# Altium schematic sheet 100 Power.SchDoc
size Letter; Organization: Toradex Solutions Inc.; Address1: 6415 Northwest Drive; Address2: Mississauga, ON, L4V 1X1; Address3: Canada
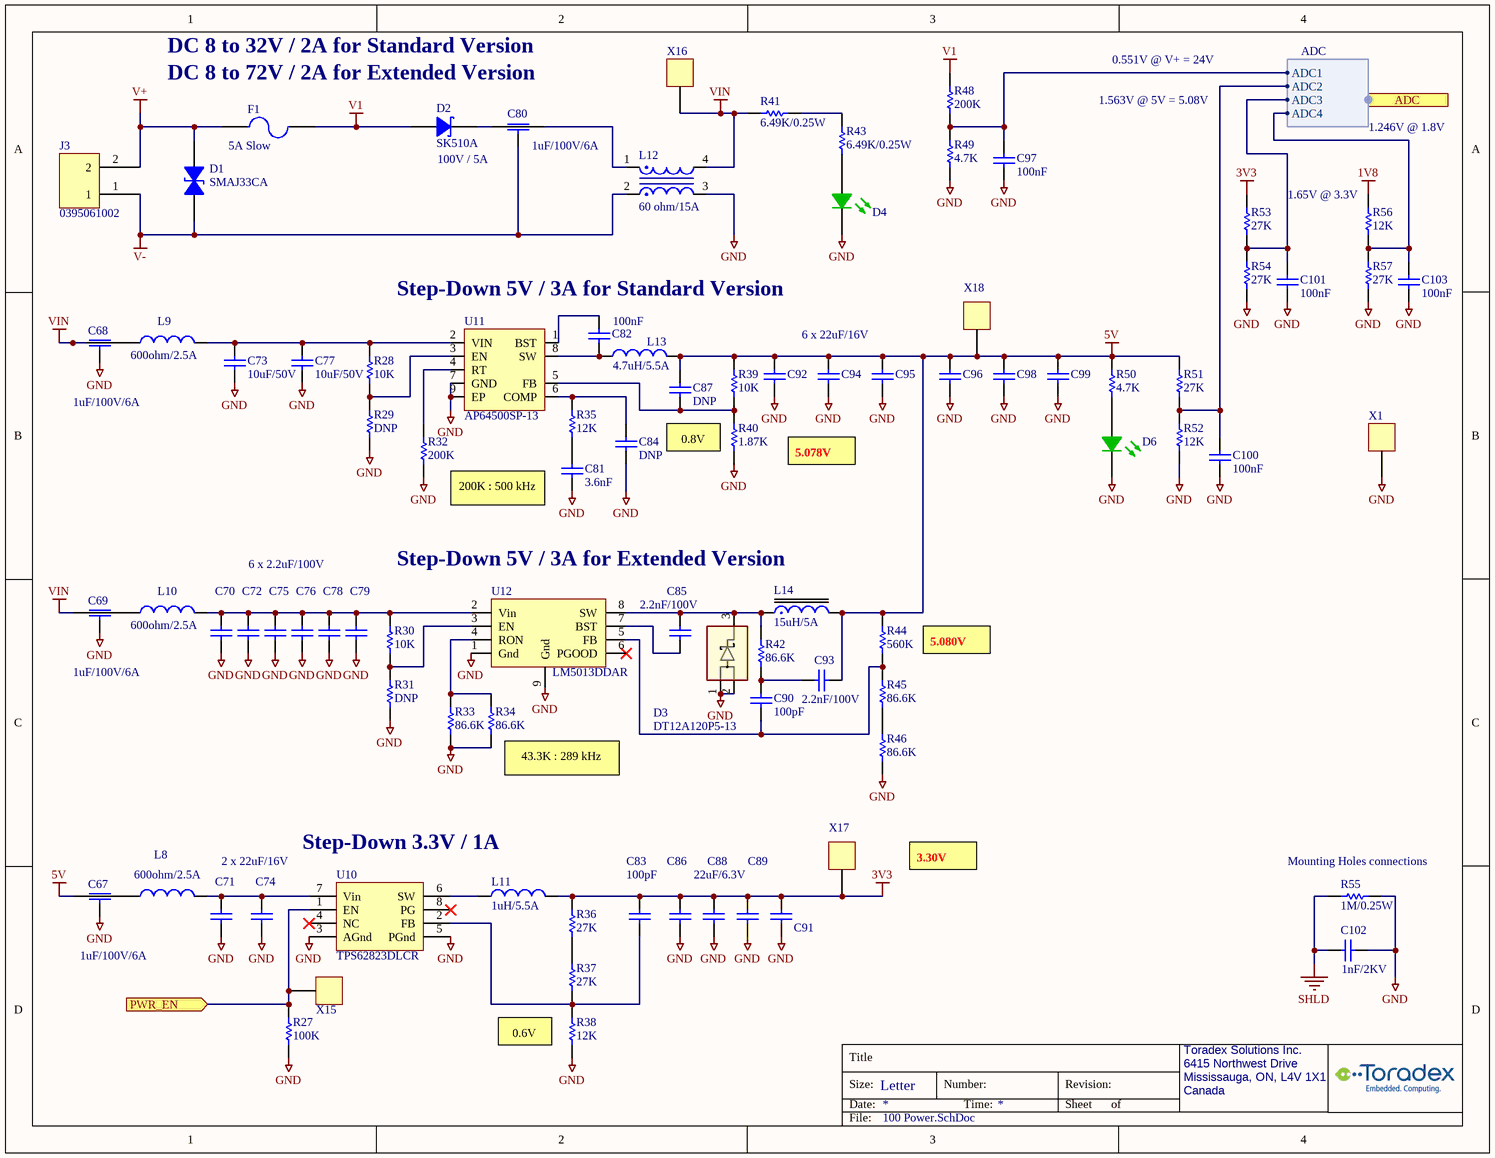
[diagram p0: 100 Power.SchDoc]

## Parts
C67  value 1uF/100V/6A  [C/1206_3P]  (hidden comment: 0753-Cap 3P-1206-1uF/100V/6A)
C68  value 1uF/100V/6A  [C/1206_3P]  (hidden comment: 0753-Cap 3P-1206-1uF/100V/6A)
C69  value 1uF/100V/6A  [C/1206_3P]  (hidden comment: 0753-Cap 3P-1206-1uF/100V/6A)
C70  CC1206KKX7R0BB225  [C/1206]  (value not drawn)
C71  1314-Cap-0805-22uF/16V  [C/0805]  (value not drawn)
C72  CC1206KKX7R0BB225  [C/1206]  (value not drawn)
C73  10uF/50V  [CAPC3225N]
C74  1314-Cap-0805-22uF/16V  [C/0805]  (value not drawn)
C75  CC1206KKX7R0BB225  [C/1206]  (value not drawn)
C76  CC1206KKX7R0BB225  [C/1206]  (value not drawn)
C77  10uF/50V  [CAPC3225N]
C78  CC1206KKX7R0BB225  [C/1206]  (value not drawn)
C79  CC1206KKX7R0BB225  [C/1206]  (value not drawn)
C80  value 1uF/100V/6A  [C/1206_3P]  (hidden comment: 0753-Cap 3P-1206-1uF/100V/6A)
C81  value 3.6nF  [C/0603]  (hidden comment: 1470-Cap-0603-3.6nF)
C82  100nF  [C0402_CAPC1005L]
C83  value 100pF  [C0402_CAPC1005L]  (hidden comment: 1602-Cap-0402-100pF)
C84  value DNP  [C/0603]  (hidden comment: 0000-Cap-0603-DNP)
C85  value 2.2nF/100V  [C/0603]  (hidden comment: 1875-Cap-0603-2.2nF/100V)
C86  22uF/6.3V  [C0402_CAPC1005L]
C87  value DNP  [C/0603]  (hidden comment: 0000-Cap-0603-DNP)
C88  22uF/6.3V  [C0402_CAPC1005L]  (value not drawn)
C89  22uF/6.3V  [C0402_CAPC1005L]  (value not drawn)
C90  value 100pF  [C0402_CAPC1005L]  (hidden comment: 1602-Cap-0402-100pF)
C91  22uF/6.3V  [C0402_CAPC1005L]  (value not drawn)
C92  1314-Cap-0805-22uF/16V  [C/0805]  (value not drawn)
C93  value 2.2nF/100V  [C/0603]  (hidden comment: 1875-Cap-0603-2.2nF/100V)
C94  1314-Cap-0805-22uF/16V  [C/0805]  (value not drawn)
C95  1314-Cap-0805-22uF/16V  [C/0805]  (value not drawn)
C96  1314-Cap-0805-22uF/16V  [C/0805]  (value not drawn)
C97  100nF  [C0402_CAPC1005L]
C98  1314-Cap-0805-22uF/16V  [C/0805]  (value not drawn)
C99  1314-Cap-0805-22uF/16V  [C/0805]  (value not drawn)
C100  100nF  [C0402_CAPC1005L]
C101  100nF  [C0402_CAPC1005L]
C102  value 1nF/2KV  [C/1206]  (hidden comment: 0567-Cap-1206-1nF/2KV)
C103  100nF  [C0402_CAPC1005L]
D1  SMAJ33CA  [SMAJ_TRANSIL]
D2  SK510A  [SMAJ]
D3  DT12A120P5-13  [POWERDI-5_DIO]
D4  Status  [LED-SMT-0603_APT1608CGCK]  (value not drawn)
D6  Status  [LED-SMT-0603_APT1608CGCK]  (value not drawn)
F1  5A Slow  [FUSC6125X279N]
J3  0395061002  [Phoenix_1727566]
L8  value 600ohm/2.5A  [INDP1206]  (hidden comment: 1641-Fer-1206-600ohm/2.5A)
L9  value 600ohm/2.5A  [INDP1206]  (hidden comment: 1641-Fer-1206-600ohm/2.5A)
L10  value 600ohm/2.5A  [INDP1206]  (hidden comment: 1641-Fer-1206-600ohm/2.5A)
L11  value 1uH/5.5A  [INDC3225N]  (hidden comment: NS10165T4R7NNA)
L12  60 ohm/15A  [COMMON_CHOKE_Laird_CM3421Y600R-10]
L13  value 4.7uH/5.5A  [INDP_7.3X6.6N]  (hidden comment: BMRA000606304R7MA1)
L14  value 15uH/5A  [EATON_DR127]  (hidden comment: DR127-150-R)
R27  value 100K  [R0402_RESC1005L]  (hidden comment: 1977-Res-0402-100K)
R28  value 10K  [R0402_RESC1005L]  (hidden comment: 1572-Res-0402-10K)
R29  value DNP  [R/0603]  (hidden comment: 0000-Res-0603-DNP)
R30  value 10K  [R0402_RESC1005L]  (hidden comment: 1572-Res-0402-10K)
R31  value DNP  [R/0603]  (hidden comment: 0000-Res-0603-DNP)
R32  value 200K  [R/0603]  (hidden comment: 1367-Res-0603-200K)
R33  value 86.6K  [R0402_RESC1005L]  (hidden comment: 1539-Res-0402-86.6k)
R34  value 86.6K  [R0402_RESC1005L]  (hidden comment: 1539-Res-0402-86.6k)
R35  value 12K  [R0402_RESC1005L]  (hidden comment: 1537-Res-0402-12K)
R36  value 27K  [R0402_RESC1005L]  (hidden comment: 1538-Res-0402-27k)
R37  value 27K  [R0402_RESC1005L]  (hidden comment: 1538-Res-0402-27k)
R38  value 12K  [R0402_RESC1005L]  (hidden comment: 1537-Res-0402-12K)
R39  value 10K  [R0402_RESC1005L]  (hidden comment: 1572-Res-0402-10K)
R40  value 1.87K  [R0402_RESC1005L]  (hidden comment: 1536-Res-0402-1.87K)
R41  value 6.49K/0.25W  [R/0805]  (hidden comment: 1603-Res-0805-6.49K/0.25W)
R42  value 86.6K  [R0402_RESC1005L]  (hidden comment: 1539-Res-0402-86.6k)
R43  value 6.49K/0.25W  [R/0805]  (hidden comment: 1603-Res-0805-6.49K/0.25W)
R44  value 560K  [R/0603]  (hidden comment: 1876-Res-0603-560K)
R45  value 86.6K  [R0402_RESC1005L]  (hidden comment: 1539-Res-0402-86.6k)
R46  value 86.6K  [R0402_RESC1005L]  (hidden comment: 1539-Res-0402-86.6k)
R48  value 200K  [R/0603]  (hidden comment: 1367-Res-0603-200K)
R49  value 4.7K  [R0402_RESC1005L]  (hidden comment: 2233-Res-0402-4.7K)
R50  value 4.7K  [R0402_RESC1005L]  (hidden comment: 2233-Res-0402-4.7K)
R51  value 27K  [R0402_RESC1005L]  (hidden comment: 1538-Res-0402-27k)
R52  value 12K  [R0402_RESC1005L]  (hidden comment: 1537-Res-0402-12K)
R53  value 27K  [R0402_RESC1005L]  (hidden comment: 1538-Res-0402-27k)
R54  value 27K  [R0402_RESC1005L]  (hidden comment: 1538-Res-0402-27k)
R55  value 1M/0.25W  [R/1206]  (hidden comment: 1860-Res-1206-1M-5%-0.25W)
R56  value 12K  [R0402_RESC1005L]  (hidden comment: 1537-Res-0402-12K)
R57  value 27K  [R0402_RESC1005L]  (hidden comment: 1538-Res-0402-27k)
U10  TPS62823DLCR  [DLC0008A]
U11  AP64500SP-13  [SOP-9 TP_ALT]
U12  LM5013DDAR  [SOP-9 TP]
X1  000-TestPoint  [TestPoint_1]  (value not drawn)
X15  000-TestPoint  [TestPoint_1]  (value not drawn)
X16  000-TestPoint  [TestPoint_1]  (value not drawn)
X17  000-TestPoint  [TestPoint_1]  (value not drawn)
X18  000-TestPoint  [TestPoint_1]  (value not drawn)

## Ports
ADC (harness ADC), PWR_EN (in)

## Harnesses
ADC: ADC1, ADC2, ADC3, ADC4

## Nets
1V8: R56.2
3V3: C83.2 C86.2 C88.2 C89.2 C91.2 L11.2 R36.2 R53.2 X17.1
5V: C67.1(In/Out) C87.1 C92.2 C93.2 C94.2 C95.2 C96.2 C98.2 C99.2 L13.2 L14.2 R39.2 R44.2 R50.2 R51.2 X18.1
GND: C67.2(Gnd) C68.2(Gnd) C69.2(Gnd) C70.1 C71.1 C72.1 C73.1 C74.1 C75.1 C76.1 C77.1 C78.1 C79.1 C81.2 C84.2 C86.1 C88.1 C89.1 C91.1 C92.1 C94.1 C95.1 C96.1 C97.2 C98.1 C99.1 C100.2 C101.2 C102.1 C103.2 D3.1 D3.2 D4.2(K) D6.2(K) L12.3 R27.1 R29.2 R31.2 R32.1 R33.1 R34.1 R38.1 R40.1 R46.1 R49.1 R52.1 R54.1 R55.2 R57.1 U10.3(AGnd) U10.5(PGnd) U11.7(GND) U11.9(EP) U12.1(Gnd) U12.9(Gnd) X1.1
SHLD: C102.2 R55.1
V1: D2.1(A) F1.2 R48.2
V+: D1.2 F1.1 J3.2
V-: C80.2(Gnd) D1.1 J3.1 L12.2
VIN: C68.1(In/Out) C69.1(In/Out) L12.4 R41.1 X16.1
PWR_EN: R27.2 U10.1(EN) X15.1 ; port PWR_EN
NetC67_3: C67.3(In/Out) L8.1
NetC68_3: C68.3(In/Out) L9.1
NetC69_3: C69.3(In/Out) L10.1
NetC70_2: C70.2 C72.2 C75.2 C76.2 C78.2 C79.2 L10.2 R30.2 U12.2(Vin)
NetC71_2: C71.2 C74.2 L8.2 U10.7(Vin)
NetC73_2: C73.2 C77.2 L9.2 R28.2 U11.2(VIN)
NetC80_1: C80.1(In/Out) D2.2(K)
NetC80_3: C80.3(In/Out) L12.1
NetC81_1: C81.1 R35.1
NetC82_1: C82.1 U11.1(BST)
NetC82_2: C82.2 L13.1 U11.8(SW)
NetC83_1: C83.1 R37.1 R38.2 U10.2(FB)
NetC84_1: C84.1 R35.2 U11.6(COMP)
NetC85_1: C85.1 D3.3 L14.1 R42.2 U12.8(SW)
NetC85_2: C85.2 U12.7(BST)
NetC87_2: C87.2 R39.1 R40.2 U11.5(FB)
NetC90_1: C90.1 R44.1 R45.2 U12.5(FB)
NetC90_2: C90.2 C93.1 R42.1
NetC97_1: C97.1 R48.1 R49.2 ; port ADC.ADC1
NetC100_1: C100.1 R51.1 R52.2 ; port ADC.ADC2
NetC101_1: C101.1 R53.1 R54.2 ; port ADC.ADC3
NetC103_1: C103.1 R56.1 R57.2 ; port ADC.ADC4
NetD4_1: D4.1(A) R43.2
NetD6_1: D6.1(A) R50.1
NetL11_1: L11.1 U10.6(SW)
NetR28_1: R28.1 R29.1 U11.3(EN)
NetR30_1: R30.1 R31.1 U12.3(EN)
NetR32_2: R32.2 U11.4(RT)
NetR33_2: R33.2 R34.2 U12.4(RON)
NetR36_1: R36.1 R37.2
NetR41_2: R41.2 R43.1
NetR45_1: R45.1 R46.2

Not connected (* = marked no-connect by the designer): U10 4(NC)* 8(PG)*; U12 6(PGOOD)*

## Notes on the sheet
- DC 8 to 32V / 2A for Standard Version
- DC 8 to 72V / 2A for Extended Version
- 1.563V @ 5V = 5.08V
- 0.551V @ V+ = 24V
- 100V / 5A
- 1.246V @ 1.8V
- (near R56) 1.65V @ 3.3V
- Step-Down 5V / 3A for Standard Version
- 6 x 22uF/16V
- 200K : 500 kHz
- (near R40) 0.8V
- 5.078V
- 6 x 2.2uF/100V
- Step-Down 5V / 3A for Extended Version
- 5.080V
- (near R34) 43.3K : 289 kHz
- 2 x 22uF/16V
- Step-Down 3.3V / 1A
- 3.30V
- (near R55) Mounting Holes connections
- 0.6V

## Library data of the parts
C67-C69 C80 = 0753-Cap 3P-1206-1uF/100V/6A: (-55 to 125 DegC) CAP FEEDTHRU 1UF 20% 100V 1206 6A; Mfr: TDK Corporation; MfrNo: YFF31HC2A105MT000N; PN: 753; Alt: YFF31AH2A105MT0Y0N
C70 C72 C75 C76 C78 C79 = 1873-Cap-1206-2.2uF/100V: (-55 to 125 DegC) CAP CER 2.2UF 100V 10% X7R 1206; Mfr: Yageo; PN: 1873
C71 C74 C92 C94-C96 C98 C99 = 1314-Cap-0805-22uF/16V: (-55 to 85 DegC) CAP CER 22uF 16V X5R 0805; MfrNo: CL21A226MOQNNNE; Mfr: Samsung; PN: 1314; Alt: CL21A226MOCLRNC,CL21A226KOQNNNG,GRM21BR61C226ME44L,EMK212BBJ226MG-T
C73 C77 = 1607-Cap-1206-10uF/50V: (-55 to 85 DegC) CAP CER 10UF 50V 10% X5R 1210; Mfr: Samsung; MfrNo: CL31A106KBHNNNE; Alt: CL31A106MBHNNNE,UMK316BBJ106ML-T,UMK316BBJ106KL-T,GRT31CR61H106ME01L,MSASU31LBB5106MTNA01; PN: 1607
C81 = 1470-Cap-0603-3.6nF: (-55 to 125 DegC) CAP CER 3600PF 50V C0G/NP0 0603; Mfr: Murata; MfrNo: GRM1885C1H362JA01D; Alt: GCM1885C1H362FA16J,C0603C362J5GAC7867,C0603C362F5GAC7867; PN: 1470
C82 C97 C100 C101 C103 = 1566-Cap-0402-100nF/50V: (-55 to 125 DegC AEC) Cap Ceramic 0.1uF 50V X7R 10% 0402; MfrNo: GRT155R71H104KE01D; Mfr: Murata; Alt: CL05B104KB54PNC,GCM155R71H104ME02D,GCM155R71H104KE02D,GCM155R71H104KE02J; PN: 1566
C83 = 1602-Cap-0402-100pF: (-55 to 125 Degc AEC) CAP CER 100PF 50V 5% NPO 0402; MfrNo: GCM1555C1H101JA16D; Mfr: Murata; PN: 1602; Alt: UMK105CH101JVHF,GRT1555C1H101JA02D,GRT1555C1H101JA02J,CL05C101JB51PNC
C84 C87 = 0000-Cap-0603-DNP: Cap 0603 DNP
C85 C93 = 1875-Cap-0603-2.2nF/100V: (-55 to 125 DegC) CAP CER 2.2nF 100V 10% X7R 0603; Mfr: KEMET; MfrNo: C0603C222K1RACTU; PN: 1875
C86 C88 C89 C91 = 2404-Cap-0402-22uF/6.3V: (-55 to 85 DegC) CAP CER 22UF 6.3V 20% X5R 0402; MfrNo: GRM155R60J226ME11D; Mfr: Murata; PN: 2404
C90 = 1602-Cap-0402-100pF: (-55 to 125 Degc AEC) CAP CER 100PF 50V 5% NPO 0402; Mfr: Murata; MfrNo: GCM1555C1H101JA16D; PN: 1602; Alt: UMK105CH101JVHF,GRT1555C1H101JA02D,GRT1555C1H101JA02J,CL05C101JB51PNC
C102 = 0567-Cap-1206-1nF/2KV: CAP CER 1000PF 2KV X7R 1206; Mfr: Johanson Dielectrics Inc.; MfrNo: 202R18W102KV4E; PN: 567; Alt: 478-2956-1-ND; Alt2: 399-4819-1-ND
D1 = 0581-SMAJ33CA: (-55 to 150 DegC) TVS DIODE 33VWM Vbrm:36.7V Vcl:53.3V 400W SMA; Mfr: Vishay Semiconductor Diodes Division; MfrNo: SMAJ33CA-E3/5A; PN: 581; Desc: (-55 to 150 DegC) TVS DIODE 33VWM Vbrm:36.7V Vstd:53.3VC SMA; Alt: SMAJ33CA-E3/61GICT-ND; Alt2: SMAJ33CABCT-ND; DR: SMAJ33CA-E3/5AGIDKR-ND; DR2: 625-SMAJ33CA-E3/5A
D2 = 1164-SK510A: (-55 to 150 DegC) DIODE SCHOTTKY 5A 100V DO-214AC SMA 850mV@5A; MfrNo: SK510A-LTP; Mfr: MCC; PN: 1164; Alt: CDBA5100-HF; Note: similar in SMB: SK510B-LTP
D3 = 2067-DT12A120P5-13: (-55 to 150 DegC) DIODE SCHOTTKY 120V 12A PowerDI; Mfr: Diodes; MfrNo: SDT12A120P5-13; PN: 2067
D4 D6 = 0333-LED Green 0603: (-40 to 85 DegC) LED GREEN 0603 50mcd; MfrNo: APT1608CGCK; Mfr: Kingbright; Alt: 754-1357-1-ND; Alt2: 160-1834-1-ND; PN: 333; DR: 754-1116-6-ND; DR2: 604-APT1608CGCK
F1 = 2235-Fuse 5A Slow 125V: (-55 to 125 DegC AEC) FUSE BOARD MOUNT 5A SLOW 125VAC/VDC; Mfr: Bel; MfrNo: 0680L5000-05; PN: 2235
J3 = 1195-Conn-Molex 2-POS R/A: (-40 to 105 DegC) TERM BLOCK HDR 2POS 90DEG RA 3.5MM 8A ScrewFlange Black; Mfr: Molex; PN: 1195; Note: plug: 0395040002,0395045002; Alt: green 0395066002
L8-L10 = 1641-Fer-1206-600ohm/2.5A: (-55 to 125 DegC AEC) FERRITE BEAD 600ohm 1206 2.5A 50mohm R@1A@150MHz:40.7ohm; Mfr: Wurth Electronics; MfrNo: 78279221601; PN: 1641; Notes: similar performance for 1A@150MHz: 742792116, 742792121, 782763301
L11 = 1618-Ind-1210-1uH/5.5A: (-40 to 125 DegC) FIXED IND 1UH I:5.5A Isat:6.5A 32mohm max 26mohm typ, full-shield SMD 1210; MfrNo: SRP3212-1R0M; Mfr: Bourns; PN: 1618; Alt: DFE322512F-1R0M=P2,DFE32CAH1R0MR0L,DFE322520F-1R0M=P2,DFE322520FD-1R0M=P2
L12 = 0598-Ind-10x6-60ohm/15A-Choke: (-40 to 125 DegC) CMC Choke 15A  60OHM 10x6x4mm 15A 0.7mohm; Mfr: Laird-Signal Integrity Products; MfrNo: CM3421Y600R-10; PN: 598; DR: 240-2501-6-ND; DR2: 875-CM3421Y600R-10
L13 = 1638-Ind-7x7x3-4.7uH-5.5A: (-55 to 125 DegC) FIXED IND 4.7UH FullShield 5.5A, 9A sat 40mohm 7.3x6.6x3.0mm; Mfr: Pulse; PN: 1638; Alt: PN1639, PN1640
L14 = 1872-Ind-12x12x8-15uH-5A: (-40 to 125 DegC) FIXED IND 15UH, 5A, 9.6A sat, 25mohm FullShield 12.5x12.5x8mm; Mfr: Eaton Cooper; PN: 1872
R27 = 1977-Res-0402-100K: (-55 to 155 DegC) RES 100K OHM 1/16W 1% 0402 SMD; Mfr: Yageo; MfrNo: RC0402FR-07100KL; PN: 1977
R28 R30 = 1572-Res-0402-10K: (-55 to 155 DegC AEC) RES 10K OHM 1% 1/16W 100ppm 0402; Mfr: Stackpole Electronics; MfrNo: RMCF0402FT10K0; PN: 1572; Alt: AC0402FR-0710KL,AC0402FR-1310KL,CRGCQ0402F10K
R29 R31 = 0000-Res-0603-DNP: RES 0603
R32 R48 = 1367-Res-0603-200K: (-55 to 155 DegC) RES SMD 200K 1% 1/10W 0603 100ppm; Mfr: Stackpole Electronics; MfrNo: RMCF0603FT200K; Alt: CR0603-FX-2003ELF,RC0603FR-07200KL,RK73H1JTTD2003F; PN: 1367
R33 R34 R42 R45 R46 = 1539-Res-0402-86.6k: (-55 to 155 DegC AEC) RES 86.6K OHM 1% 1/16W 100ppm 0402; Mfr: Stackpole Electronics; MfrNo: RMCF0402FT86K6; Alt: AC0402FR-0786K6L,RK73H1ETTP8662F,ERJ-2RKF8662X; PN: 1539
R35 R38 R52 R56 = 1537-Res-0402-12K: (-55 to 155 DegC AEC) RES 12K OHM 1% 1/16W 100ppm 0402; Mfr: Stackpole Electronics; MfrNo: RMCF0402FT12K0; Alt: AC0402FR-0712KL,CRGCQ0402F12K; PN: 1537
R36 R37 R51 R53 R54 R57 = 1538-Res-0402-27k: (-55 to 155 DegC AEC) RES 27K OHM 1% 1/16W 100ppm 0402; Mfr: Stackpole Electronics; MfrNo: RMCF0402FT27K0; PN: 1538; Alt: AC0402FR-0727KL,CRGCQ0402F27K
R39 = 1572-Res-0402-10K: (-55 to 155 DegC AEC) RES 10K OHM 1% 1/16W 100ppm 0402; Mfr: Stackpole Electronics; MfrNo: RMCF0402FT10K0; Alt: AC0402FR-0710KL,AC0402FR-1310KL,CRGCQ0402F10K; PN: 1572
R40 = 1536-Res-0402-1.87K: (-55 to 155 DegC AEC) RES 1.87K OHM 1% 1/16W 100ppm 0402; MfrNo: RMCF0402FT1K87; Mfr: Stackpole Electronics; Alt: AC0402FR-071K87L,RK73H1ETTP1871F,ERJ-2RKF1871X; PN: 1536
R41 R43 = 1603-Res-0805-6.49K/0.25W: (-55 to 155 DegC AEC) RES 6.49K OHM 1% 0.25W 0805 100ppm; Mfr: KOA Speer; MfrNo: RK73H2ATTD6491F; Alt: RCS08056K49FKEA,CRCW08056K49FKEAHP; PN: 1603
R44 = 1876-Res-0603-560K: (-55 to 155 DegC AEC) RES SMD 560K 1% 1/10W 0603 100ppm; Mfr: Stackpole Electronics; MfrNo: RMCF0603FT560K; PN: 1876
R49 R50 = 2233-Res-0402-4.7K: (-55 to 155 DegC) RES 4.70K OHM 1/16W 1% 0402 100ppm; MfrNo: RC0402FR-074K7L; Mfr: Yageo; PN: 2233
R55 = 1860-Res-1206-1M-5%-0.25W: (-55 to 155 DegC) RES SMD 1M OHM 5% 0.25W 10ppm 1206; Mfr: TE Connectivity; MfrNo: CRGCQ1206J1M0; PN: 1860; Alt: RMCF1206JT1M00, RMCF1206JG1M00, CR1206-JW-105ELF
U10 = 1619-TPS62823: (-40 to 125 DegC) IC  IC REG BUCK ADJ 2.2MHz Vin:2.4-5.5V Io:3A Sync 8-VFDFN 8VSON-HR; Mfr: Texas Instruments; PN: 1619; Alt: TPS62823DLCT; Note: similar with smaller output current: TPS62822DLC, TPS62821DLC
U11 = 1362-AP64500SP-13: (-40 to 85 DegC) IC REG BUCK ADJ Sync 5A Vin:3.8 to 40V 100-2200kHz FSS (spread spectrum) MaxDuty:100% SO-8EP; Mfr: Diodes; PN: 1362; Alt: AP64500QSP-13; Note: similar: AP64501 PN1392
U12 = 2063-LM5013DDAR: (-40 to 150 DegC) IC REG BUCK ADJ 3.5A 8-POWERSOIC 1MHz 100V; Mfr: Texas Instruments; PN: 2063
X1 X15-X18 = 000-TestPoint: Note: this is PCB footprint only, no parts to buy or assemble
